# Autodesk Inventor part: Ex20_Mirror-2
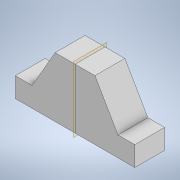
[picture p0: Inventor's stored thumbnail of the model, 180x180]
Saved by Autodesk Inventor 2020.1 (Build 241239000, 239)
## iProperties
Created: 2019-11
Part Number: Ex20_Mirror-2
Material: Generic
Document SubType Name: Modeling
Designer: Synergysoft Dell02
Density: 1 g/cm^3
Appearance: Default
Author: Synergysoft Dell02
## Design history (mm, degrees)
sketch "Sketch1"
  geometry: L1 (0, 30)-(-10, 30); L2 (-10, 30)-(-21.547, 10); L3 (-21.547, 10)-(-30, 10); L4 (-30, 10)-(-30, 0); L5 (-30, 0)-(0, 0); L6 (0, 0)-(0, 30)
  constraints: 12 end point, 3 perpendicular, 1 horizontal, 1 parallel
  dimensions: "d0" = 10 distance between parallel lines of L5 L3; "d1" = 30 deg angle of L6 L2; "d2" = 30 distance of L5.end L1.start; "d3" = 30 distance between parallel lines of L6 L4; "d4" = 10 distance of L1.start L1.end
extrude "Extrusion1" new body sketch "Sketch1" distance "d5" = 15; taper "d6" = 0 deg
mirror "Mirror1"
body "Solid1"
feature "Pattern of Solid1:1"
body "Solid2"
